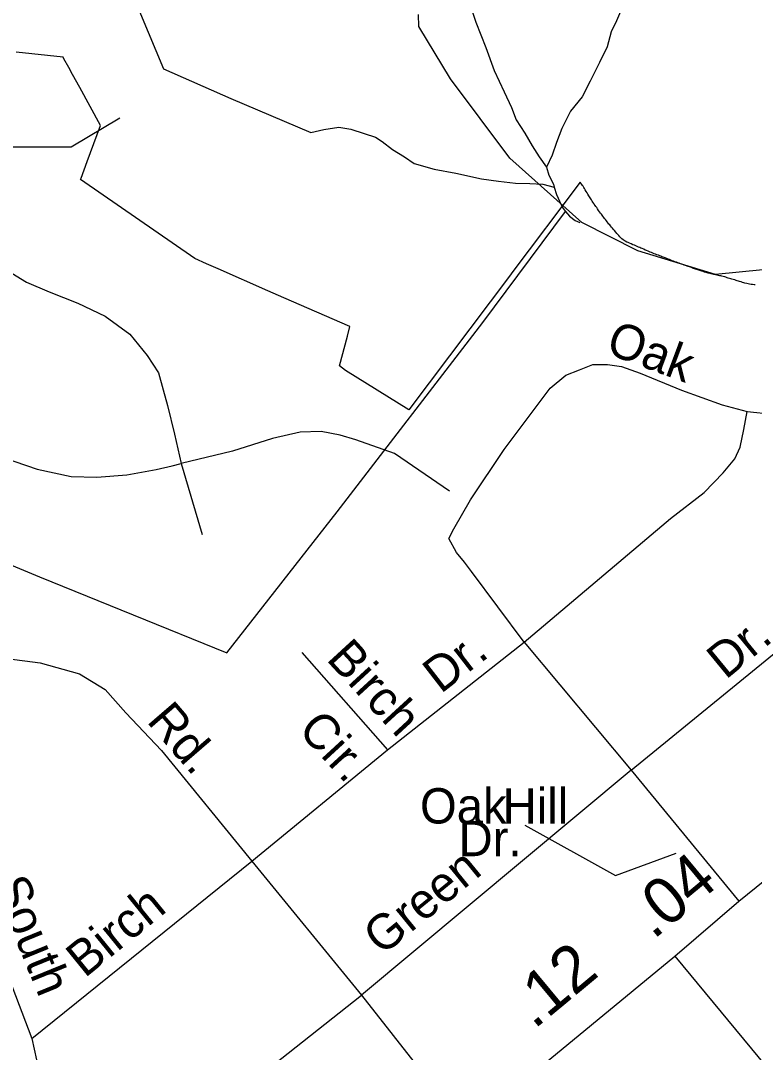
# Model space of a CAD drawing. Extents: x 2315291 to 2336543, y 597177 to 615230.
# Drawn here: x 2321792 to 2323766, y 599288 to 602063 of the extents above; entities that cross this region are included whole.
import ezdxf

# ---------------------------------------------------------------- set-up
doc = ezdxf.new("R2010")
doc.units = 0
for name, color, linetype in [('Exist Boundary Political City Limit New', 7, 'Continuous'), ('Exist Hydrographic Creek Single Shore', 7, 'Continuous'), ('Exist Hydrographic Misc Water Feature', 7, 'Continuous'), ('Exist Road Non-System Type 51', 7, 'Continuous'), ('Exist Road Non-System Type 51 Label', 7, 'Continuous'), ('Exist Road Primary US Attributed', 7, 'Continuous'), ('Exist Road Primary US Mileage Tenths English Label', 7, 'Continuous'), ('Map Preparation Boundary City Limit Buffer Line', 7, 'Continuous')]:
    doc.layers.add(name, color=color, linetype=linetype)

msp = doc.modelspace()

# ---------------------------------------------------------------- linework, layer by layer
at = {"layer": 'Exist Boundary Political City Limit New'}
for points in [[(2323430, 601464.5), (2323426.5, 601466.1), (2323422.8, 601467.8), (2323418.5, 601469.8), (2323415.8, 601471.6), (2323412.8, 601474.1), (2323409.5, 601476.6), (2323406.5, 601479.1), (2323404, 601481.5), (2323401, 601484.9), (2323398.2, 601487.9), (2323395.8, 601490.9), (2323393, 601494.2), (2323389.2, 601498.6), (2323386.8, 601501.7), (2323384.2, 601504.8), (2323381.5, 601508.1), (2323379, 601510.9), (2323376.5, 601513.9), (2323374.5, 601516.2), (2323372.5, 601518.6), (2323369.8, 601522), (2323367.8, 601524.8), (2323365.2, 601528), (2323363, 601531.2), (2323360.8, 601534.1), (2323358.5, 601537.3), (2323356.2, 601540.1), (2323354.5, 601542.4), (2323352, 601545.6), (2323349.5, 601548.8), (2323346.8, 601552.6), (2323343.8, 601556.9), (2323341.5, 601560.2), (2323339.2, 601563.5), (2323337.2, 601566.4), (2323335.2, 601569.3), (2323333.8, 601571.8), (2323331.5, 601575.2), (2323329.8, 601577.8), (2323327.5, 601581.5), (2323325.5, 601584.4), (2323324, 601586.9), (2323322.2, 601589.4), (2323320.8, 601591.9), (2323317.8, 601596.4), (2323315.5, 601600.4), (2323313.5, 601603.9), (2323310.8, 601608.6), (2323309, 601611.6), (2323307.2, 601614.2), (2323305, 601617.6), (2323303.2, 601620), (2323301.8, 601622.5), (2323299.2, 601626), (2323297, 601629.1), (2323113.5, 601384.9), (2323109.5, 601379.8), (2322836, 601016.4), (2322665.8, 601122.3), (2322649.2, 601134.8), (2322670.8, 601214.8), (2322677.8, 601240.9), (2322500, 601317.9), (2322457, 601336.8), (2322323, 601395.5), (2322291.8, 601409.1), (2322260, 601423.1), (2321953.2, 601636.3), (2321954.2, 601639.1), (2321971, 601684.6), (2322006.5, 601781.5), (2321950.8, 601883.1), (2321931.5, 601918.1), (2321921, 601937.2), (2321908.2, 601960.6), (2321905.8, 601965.2), (2321779.8, 601978)], [(2323768, 601352.8), (2323765, 601353), (2323760.5, 601353.3), (2323757.5, 601353.6), (2323753, 601354.3), (2323749.2, 601355.1), (2323745.2, 601355.9), (2323740.5, 601357), (2323737.5, 601357.9), (2323733.8, 601359.2), (2323730, 601360.4), (2323726.2, 601361.7), (2323723.2, 601362.6), (2323719.5, 601363.8), (2323716.5, 601364.7), (2323712.8, 601365.8), (2323709, 601366.8), (2323705.5, 601367.8), (2323702.2, 601368.8), (2323699.2, 601369.6), (2323695.5, 601370.8), (2323692.8, 601371.8), (2323689, 601372.9), (2323686, 601373.9), (2323682.2, 601374.9), (2323678.2, 601375.8), (2323675.2, 601376.5), (2323672, 601377.3), (2323668, 601378.2), (2323664.5, 601378.9), (2323660.8, 601379.8), (2323656.8, 601380.6), (2323653.8, 601381.2), (2323650, 601382.2), (2323647, 601382.9), (2323644.2, 601383.7), (2323641.2, 601384.4), (2323636.2, 601385.8), (2323631.8, 601387.1), (2323627.8, 601388.2), (2323624, 601389.4), (2323619.5, 601390.9), (2323616.5, 601391.9), (2323613.5, 601392.9), (2323610.8, 601393.9), (2323607, 601395.2), (2323602.2, 601396.8), (2323599.5, 601397.8), (2323596.5, 601398.9), (2323593.8, 601399.9), (2323591, 601400.9), (2323588, 601401.9), (2323584.8, 601403.1), (2323580.5, 601404.6), (2323576.8, 601405.9), (2323573, 601407.3), (2323570.2, 601408.3), (2323567.2, 601409.3), (2323563.5, 601410.7), (2323559.8, 601412.1), (2323556, 601413.4), (2323552, 601414.9), (2323548.5, 601416.2), (2323544.8, 601417.6), (2323541, 601419.1), (2323537.8, 601420.4), (2323534, 601421.8), (2323530, 601423.4), (2323526.2, 601424.9), (2323520.8, 601427.1), (2323517.2, 601428.4), (2323514, 601429.6), (2323511.2, 601430.7), (2323507.5, 601432.1), (2323503.8, 601433.6), (2323499.8, 601435.1), (2323496.2, 601436.4), (2323492.8, 601437.9), (2323489, 601439.3), (2323485.2, 601440.8), (2323479.8, 601443.1), (2323476, 601444.7), (2323472.2, 601446.3), (2323468, 601448.2), (2323463.8, 601450.1), (2323460.5, 601451.6), (2323457.8, 601452.8), (2323454, 601454.4), (2323450.8, 601455.8), (2323446.8, 601457.6), (2323443, 601459.1), (2323439.2, 601460.6), (2323434.2, 601462.7), (2323430, 601464.5)]]:
    msp.add_lwpolyline(points, dxfattribs=at)
at = {"layer": 'Exist Hydrographic Creek Single Shore'}
msp.add_lwpolyline([(2325385.4, 599067.9), (2325242.4, 599173.7), (2325115.3, 599365.4), (2325030.4, 599529.4), (2325030.4, 599572), (2325013.4, 599597.6), (2324926.5, 599945.2), (2324925.4, 600053.4), (2324847.3, 600329.2), (2324775.3, 600792.3), (2324741.3, 600886.1), (2324615.4, 601015.5), (2324431.3, 601096.7), (2324329.3, 601187.7), (2324278.3, 601287.4), (2324178.4, 601378.5), (2324052.3, 601419.4), (2323661.3, 601380.6), (2323452.3, 601444.4), (2323301.4, 601520.3), (2323108.3, 601692.9), (2322948.3, 601906.3), (2322863.2, 602047.3), (2322862.4, 602080.1)], dxfattribs=at)
at = {"layer": 'Exist Hydrographic Misc Water Feature'}
for points in [[(2322481, 602960.8), (2322523, 602805.2), (2322529, 602771.5), (2322555.4, 602729.7), (2322607.9, 602672.4), (2322675, 602597), (2322735.7, 602517.7), (2322778.3, 602482.1), (2322830.8, 602422.7), (2322869.2, 602375.1), (2322920, 602279.9), (2322963.3, 602194.3), (2322998.1, 602112.8), (2323016.8, 602058.9), (2323043.5, 601991.2), (2323065.8, 601929.5), (2323092.9, 601871.9), (2323112.6, 601830), (2323125.3, 601796), (2323147.8, 601760.6), (2323168.1, 601726.7), (2323186.4, 601696.8), (2323206.5, 601669.1)], [(2321911.8, 602556.9), (2322026.8, 602290.2), (2322176.1, 601934), (2322357.1, 601854.1), (2322572.2, 601762), (2322607.5, 601770.5), (2322647.7, 601777.1), (2322679.9, 601771.4), (2322715.8, 601759.9), (2322746.1, 601750.1), (2322764.2, 601738.5), (2322792.5, 601716.8), (2322824.9, 601696.9), (2322850.3, 601679.3), (2322904.6, 601663.8), (2322962.9, 601652.6), (2323031.2, 601637.4), (2323077.1, 601631.7), (2323123, 601626.5), (2323161.4, 601624.8), (2323197, 601623), (2323227, 601615.3)], [(2323458.1, 602475.5), (2323455.8, 602467.3), (2323466.1, 602455.6), (2323472.2, 602425.5), (2323470.6, 602405.5), (2323471, 602359.6), (2323473.5, 602315.8), (2323471.8, 602277.5), (2323464.2, 602231.7), (2323454.8, 602205.5), (2323437, 602163.2), (2323415.6, 602111.2), (2323394.5, 602062.9), (2323380.6, 602033), (2323369.3, 601992.9), (2323349.4, 601950.5), (2323324, 601900.4), (2323302.6, 601858.2), (2323271.1, 601819.9), (2323247.7, 601773.5), (2323233.7, 601735.5), (2323222.1, 601701.1), (2323206.5, 601669.1)], [(2323206.5, 601669.1), (2323212.6, 601647.4), (2323225.1, 601623.2), (2323227, 601615.3)], [(2323227, 601615.3), (2323233.3, 601595.2), (2323245.8, 601567.8), (2323251.8, 601557.6), (2323257.7, 601549.8)], [(2320143.8, 601160.7), (2320239.2, 601209.6), (2320544.1, 601304.9), (2320856.8, 601404.2), (2320910.3, 601258.7), (2320957.9, 601113.2), (2321185.3, 600931.8), (2321429.5, 600738.5), (2321842.9, 600567.2), (2322346.9, 600362.8), (2322643, 600741.7), (2323035.1, 601251.6), (2323257.7, 601549.8)], [(2323257.7, 601549.8), (2323268, 601537.7), (2323283.8, 601526), (2323296.1, 601520.1)]]:
    msp.add_lwpolyline(points, dxfattribs=at)
at = {"layer": 'Exist Road Non-System Type 51'}
for p, q in [((2322223.5, 600871.9), (2322280.3, 600681.1)), ((2323434.4, 600047.1), (2324225.1, 600694.3)), ((2322778.8, 600101.9), (2323146.4, 600392)), ((2323146.4, 600392), (2323434.4, 600047.1)), ((2322413.8, 599803), (2322778.8, 600101.9)), ((2323434.4, 600047.1), (2322708.5, 599441.8)), ((2323434.4, 600047.1), (2323723.6, 599695.4)), ((2321821.7, 599325.5), (2322413.8, 599803)), ((2322413.8, 599803), (2322708.5, 599441.8)), ((2323552, 599546.7), (2323826.4, 599215.3)), ((2322708.5, 599441.8), (2322989.6, 599086.8))]:
    msp.add_line(p, q, dxfattribs=at)
for points in [[(2321465.2, 601622.5), (2321588.9, 601522.1), (2321655.8, 601465.3), (2321745, 601398.3), (2321807.9, 601359.8), (2321868.7, 601333.4), (2321945.8, 601303), (2322018.8, 601268.5), (2322085.7, 601219.8), (2322132.3, 601163), (2322162.7, 601116.3), (2322174.9, 601070.7), (2322187, 601028.1), (2322205.3, 600951), (2322223.5, 600871.9)], [(2321132.7, 601290.8), (2321193.5, 601260.4), (2321262.5, 601203.6), (2321372, 601100.1), (2321471.3, 601025), (2321532.1, 600984.5), (2321712.6, 600899.2), (2321836.3, 600856.6), (2321927.5, 600837.4), (2321996.5, 600835.3), (2322077.6, 600841.4), (2322156.6, 600855.6), (2322199.2, 600865.8), (2322223.5, 600871.9)], [(2323146.4, 600392), (2323004.4, 600581.3), (2322985.6, 600607.1), (2322964, 600632.8), (2322943.7, 600670.6), (2322957.2, 600696.3), (2323001.8, 600774.8), (2323092.4, 600910.1), (2323216.7, 601075.1), (2323258.6, 601109.6), (2323295.1, 601124.4), (2323331.6, 601138), (2323370.8, 601138), (2323408.7, 601132.6), (2323458.7, 601115), (2323569.5, 601069), (2323679, 601029.8), (2323746.6, 601012.2)], [(2323146.4, 600392), (2323539.8, 600724.1), (2323630.4, 600794.4), (2323681.7, 600847.2), (2323712.8, 600885), (2323727.7, 600916.1), (2323737.1, 600963.5), (2323746.6, 601012.2)], [(2323746.6, 601012.2), (2323815.5, 601004.7), (2323889.9, 600995.3), (2323939.9, 600985.8), (2323976.4, 600970.9), (2324016.9, 600943.9), (2324065.6, 600897.2), (2324141.3, 600802.5), (2324225.1, 600694.3)], [(2322945.4, 600797.8), (2322797.4, 600899.2), (2322693.9, 600935.8), (2322651.4, 600947.9), (2322600.7, 600958.1), (2322543.9, 600956.1), (2322468.9, 600939.8), (2322361.4, 600905.3), (2322223.5, 600871.9)], [(2322548, 600363.6), (2322778.8, 600101.9)], [(2321255.4, 600184.4), (2321441.9, 600266.9), (2321571.7, 600310.2), (2321640.6, 600335.9), (2321689.3, 600348.1), (2321754.2, 600348.1), (2321844.7, 600335.9), (2321950.2, 600306.1), (2322019.1, 600264.2), (2322074.5, 600202), (2322170.5, 600100.5), (2322413.8, 599803)], [(2321620.3, 599828.7), (2321716.3, 599601.4), (2321821.7, 599325.5)], [(2321821.7, 599325.5), (2321916.4, 598895.4), (2321925.8, 598856.2), (2321933.9, 598835.9), (2321944.7, 598830.5), (2321959.6, 598838.6), (2322258.3, 599086.1), (2322708.5, 599441.8)]]:
    msp.add_lwpolyline(points, dxfattribs=at)
at = {"layer": 'Exist Road Non-System Type 51 Label'}
for points in [[(2322058.3, 601801.1), (2321928, 601722.9), (2321715.7, 601722.9)], [(2323148.6, 599899.3), (2323391.9, 599763.8), (2323555, 599824)]]:
    msp.add_lwpolyline(points, dxfattribs=at)
at = {"layer": 'Exist Road Primary US Attributed'}
msp.add_lwpolyline([(2321872.6, 598168.2), (2322100.6, 598357.7), (2322368.8, 598574.3), (2322589.4, 598759.9), (2322822.5, 598950.5), (2322989.6, 599086.8), (2323103.2, 599177.4), (2323552, 599546.7), (2323723.6, 599695.4), (2324757.7, 600529.3), (2324925.6, 600670.6), (2324932.1, 600676), (2324968.9, 600707), (2325301.4, 600984), (2325554.9, 601184.8), (2325709, 601298.4), (2326037.4, 601569.3), (2326353.8, 601821.9), (2326377, 601842), (2326507.1, 601954.4)], dxfattribs=at)
at = {"layer": 'Map Preparation Boundary City Limit Buffer Line'}
for points in [[(2323430, 601464.5), (2323426.5, 601466.1), (2323422.8, 601467.8), (2323418.5, 601469.8), (2323415.8, 601471.6), (2323412.8, 601474.1), (2323409.5, 601476.6), (2323406.5, 601479.1), (2323404, 601481.5), (2323401, 601484.9), (2323398.2, 601487.9), (2323395.8, 601490.9), (2323393, 601494.2), (2323389.2, 601498.6), (2323386.8, 601501.7), (2323384.2, 601504.8), (2323381.5, 601508.1), (2323379, 601510.9), (2323376.5, 601513.9), (2323374.5, 601516.2), (2323372.5, 601518.6), (2323369.8, 601522), (2323367.8, 601524.8), (2323365.2, 601528), (2323363, 601531.2), (2323360.8, 601534.1), (2323358.5, 601537.3), (2323356.2, 601540.1), (2323354.5, 601542.4), (2323352, 601545.6), (2323349.5, 601548.8), (2323346.8, 601552.6), (2323343.8, 601556.9), (2323341.5, 601560.2), (2323339.2, 601563.5), (2323337.2, 601566.4), (2323335.2, 601569.3), (2323333.8, 601571.8), (2323331.5, 601575.2), (2323329.8, 601577.8), (2323327.5, 601581.5), (2323325.5, 601584.4), (2323324, 601586.9), (2323322.2, 601589.4), (2323320.8, 601591.9), (2323317.8, 601596.4), (2323315.5, 601600.4), (2323313.5, 601603.9), (2323310.8, 601608.6), (2323309, 601611.6), (2323307.2, 601614.2), (2323305, 601617.6), (2323303.2, 601620), (2323301.8, 601622.5), (2323299.2, 601626), (2323297, 601629.1), (2323113.5, 601384.9), (2323109.5, 601379.8), (2322836, 601016.4), (2322665.8, 601122.3), (2322649.2, 601134.8), (2322670.8, 601214.8), (2322677.8, 601240.9), (2322500, 601317.9), (2322457, 601336.8), (2322323, 601395.5), (2322291.8, 601409.1), (2322260, 601423.1), (2321953.2, 601636.3), (2321954.2, 601639.1), (2321971, 601684.6), (2322006.5, 601781.5), (2321950.8, 601883.1), (2321931.5, 601918.1), (2321921, 601937.2), (2321908.2, 601960.6), (2321905.8, 601965.2), (2321779.8, 601978)], [(2323768, 601352.8), (2323765, 601353), (2323760.5, 601353.3), (2323757.5, 601353.6), (2323753, 601354.3), (2323749.2, 601355.1), (2323745.2, 601355.9), (2323740.5, 601357), (2323737.5, 601357.9), (2323733.8, 601359.2), (2323730, 601360.4), (2323726.2, 601361.7), (2323723.2, 601362.6), (2323719.5, 601363.8), (2323716.5, 601364.7), (2323712.8, 601365.8), (2323709, 601366.8), (2323705.5, 601367.8), (2323702.2, 601368.8), (2323699.2, 601369.6), (2323695.5, 601370.8), (2323692.8, 601371.8), (2323689, 601372.9), (2323686, 601373.9), (2323682.2, 601374.9), (2323678.2, 601375.8), (2323675.2, 601376.5), (2323672, 601377.3), (2323668, 601378.2), (2323664.5, 601378.9), (2323660.8, 601379.8), (2323656.8, 601380.6), (2323653.8, 601381.2), (2323650, 601382.2), (2323647, 601382.9), (2323644.2, 601383.7), (2323641.2, 601384.4), (2323636.2, 601385.8), (2323631.8, 601387.1), (2323627.8, 601388.2), (2323624, 601389.4), (2323619.5, 601390.9), (2323616.5, 601391.9), (2323613.5, 601392.9), (2323610.8, 601393.9), (2323607, 601395.2), (2323602.2, 601396.8), (2323599.5, 601397.8), (2323596.5, 601398.9), (2323593.8, 601399.9), (2323591, 601400.9), (2323588, 601401.9), (2323584.8, 601403.1), (2323580.5, 601404.6), (2323576.8, 601405.9), (2323573, 601407.3), (2323570.2, 601408.3), (2323567.2, 601409.3), (2323563.5, 601410.7), (2323559.8, 601412.1), (2323556, 601413.4), (2323552, 601414.9), (2323548.5, 601416.2), (2323544.8, 601417.6), (2323541, 601419.1), (2323537.8, 601420.4), (2323534, 601421.8), (2323530, 601423.4), (2323526.2, 601424.9), (2323520.8, 601427.1), (2323517.2, 601428.4), (2323514, 601429.6), (2323511.2, 601430.7), (2323507.5, 601432.1), (2323503.8, 601433.6), (2323499.8, 601435.1), (2323496.2, 601436.4), (2323492.8, 601437.9), (2323489, 601439.3), (2323485.2, 601440.8), (2323479.8, 601443.1), (2323476, 601444.7), (2323472.2, 601446.3), (2323468, 601448.2), (2323463.8, 601450.1), (2323460.5, 601451.6), (2323457.8, 601452.8), (2323454, 601454.4), (2323450.8, 601455.8), (2323446.8, 601457.6), (2323443, 601459.1), (2323439.2, 601460.6), (2323434.2, 601462.7), (2323430, 601464.5)]]:
    msp.add_lwpolyline(points, dxfattribs=at)

# ---------------------------------------------------------------- texts
at = {"layer": 'Exist Road Non-System Type 51 Label'}
for s, rotation, p in [('Oak', 339.5154, (2323362.4, 601170.2)), ('Dr.', 39.4242, (2323688.5, 600289.2)), ('Birch', 312.5504, (2322611.7, 600344.9)), ('Dr.', 37.7708, (2322921.9, 600251.3)), ('Rd.', 310.7842, (2322128.5, 600178.4)), ('Cir.', 312.5504, (2322534.9, 600153.7)), ('Green', 39.2338, (2322763.8, 599546.5)), ('South', 292.2219, (2321717.1, 599740.1)), ('Birch', 39.0932, (2321964.1, 599486.8))]:
    msp.add_text(s, height=95, rotation=rotation, dxfattribs=at).set_placement(p)
for s, p in [('Oak', (2322866.2, 599903.9)), ('Hill', (2323088.4, 599903.9)), ('Dr.', (2322970, 599816))]:
    msp.add_text(s, height=95, dxfattribs=at).set_placement(p)
at = {"layer": 'Exist Road Primary US Mileage Tenths English Label'}
for s, p in [('.04', (2323493.9, 599589.9)), ('.12', (2323173.1, 599348.7))]:
    msp.add_text(s, height=125, rotation=39.6946, dxfattribs=at).set_placement(p)

doc.saveas('drawing.dxf')
